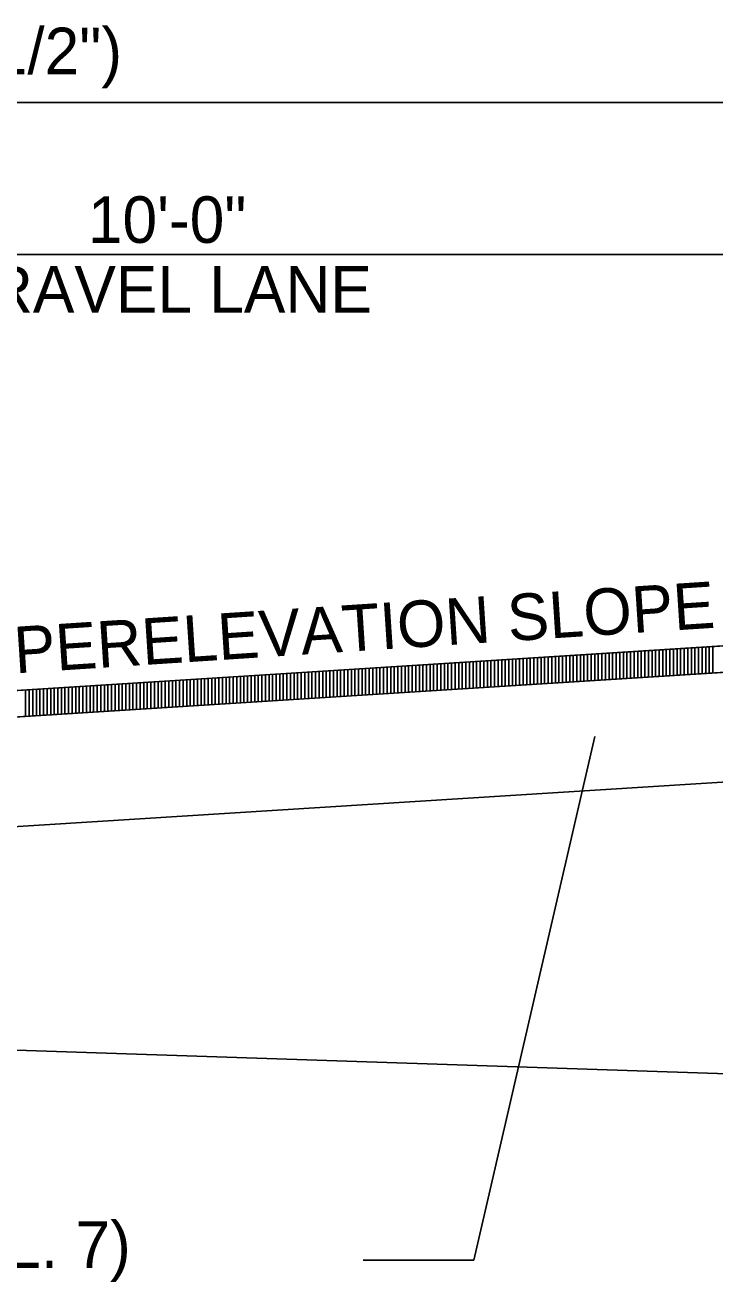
# Model space of a CAD drawing. Extents: x 1373719 to 1374161, y 379835 to 380167.
# Drawn here: x 1373967.18 to 1373976.82, y 379916.4 to 379933.96 of the extents above; entities that cross this region are included whole.
import ezdxf

# ---------------------------------------------------------------- set-up
doc = ezdxf.new("R2010")
doc.units = 0
for name, color, linetype in [('ACHM Surface', 7, 'Continuous'), ('Agg Base Course Text', 7, 'Continuous'), ('GREEN_TXT', 7, 'Continuous'), ('Pavement Layers', 7, 'Continuous'), ('SIGNATURE', 7, 'Continuous'), ('T_Drafting', 7, 'Continuous')]:
    doc.layers.add(name, color=color, linetype=linetype)

msp = doc.modelspace()

# ---------------------------------------------------------------- linework, layer by layer
for p, q in [((1373962.025, 379924.35), (1373981.525, 379925.58)), ((1373962.025, 379922.447), (1373986.325, 379923.98))]:
    msp.add_line(p, q)
at = {"layer": 'ACHM Surface'}
for p, q in [((1373975.388, 379924.823), (1373975.388, 379925.193)), ((1373975.438, 379924.826), (1373975.438, 379925.196)), ((1373975.488, 379924.829), (1373975.488, 379925.199)), ((1373975.538, 379924.832), (1373975.538, 379925.202)), ((1373975.588, 379924.835), (1373975.588, 379925.205)), ((1373975.638, 379924.838), (1373975.638, 379925.209)), ((1373975.688, 379924.842), (1373975.688, 379925.212)), ((1373975.738, 379924.845), (1373975.738, 379925.215)), ((1373975.788, 379924.848), (1373975.788, 379925.218)), ((1373975.838, 379924.851), (1373975.838, 379925.221)), ((1373975.888, 379924.854), (1373975.888, 379925.224)), ((1373975.938, 379924.857), (1373975.938, 379925.228)), ((1373975.988, 379924.86), (1373975.988, 379925.231)), ((1373976.038, 379924.864), (1373976.038, 379925.234)), ((1373976.088, 379924.867), (1373976.088, 379925.237)), ((1373976.138, 379924.87), (1373976.138, 379925.24)), ((1373976.188, 379924.873), (1373976.188, 379925.243)), ((1373976.238, 379924.876), (1373976.238, 379925.247)), ((1373976.288, 379924.879), (1373976.288, 379925.25)), ((1373976.338, 379924.883), (1373976.338, 379925.253)), ((1373976.388, 379924.886), (1373976.388, 379925.256)), ((1373976.438, 379924.889), (1373976.438, 379925.259)), ((1373976.488, 379924.892), (1373976.488, 379925.262)), ((1373976.538, 379924.895), (1373976.538, 379925.265)), ((1373976.588, 379924.898), (1373976.588, 379925.269)), ((1373976.638, 379924.902), (1373976.638, 379925.272)), ((1373976.688, 379924.905), (1373976.688, 379925.275)), ((1373976.738, 379924.908), (1373976.738, 379925.278)), ((1373976.788, 379924.911), (1373976.788, 379925.281)), ((1373972.638, 379924.649), (1373972.638, 379925.019)), ((1373972.688, 379924.652), (1373972.688, 379925.022)), ((1373972.738, 379924.655), (1373972.738, 379925.026)), ((1373972.788, 379924.659), (1373972.788, 379925.029)), ((1373972.838, 379924.662), (1373972.838, 379925.032)), ((1373972.888, 379924.665), (1373972.888, 379925.035)), ((1373972.938, 379924.668), (1373972.938, 379925.038)), ((1373972.988, 379924.671), (1373972.988, 379925.041)), ((1373973.038, 379924.674), (1373973.038, 379925.045)), ((1373973.088, 379924.677), (1373973.088, 379925.048)), ((1373973.138, 379924.681), (1373973.138, 379925.051)), ((1373973.188, 379924.684), (1373973.188, 379925.054)), ((1373973.238, 379924.687), (1373973.238, 379925.057)), ((1373973.288, 379924.69), (1373973.288, 379925.06)), ((1373973.338, 379924.693), (1373973.338, 379925.064)), ((1373973.388, 379924.696), (1373973.388, 379925.067)), ((1373973.438, 379924.7), (1373973.438, 379925.07)), ((1373973.488, 379924.703), (1373973.488, 379925.073)), ((1373973.538, 379924.706), (1373973.538, 379925.076)), ((1373973.588, 379924.709), (1373973.588, 379925.079)), ((1373973.638, 379924.712), (1373973.638, 379925.082)), ((1373973.688, 379924.715), (1373973.688, 379925.086)), ((1373973.738, 379924.719), (1373973.738, 379925.089)), ((1373973.788, 379924.722), (1373973.788, 379925.092)), ((1373973.838, 379924.725), (1373973.838, 379925.095)), ((1373973.888, 379924.728), (1373973.888, 379925.098)), ((1373973.938, 379924.731), (1373973.938, 379925.101)), ((1373973.988, 379924.734), (1373973.988, 379925.105)), ((1373974.038, 379924.737), (1373974.038, 379925.108)), ((1373974.088, 379924.741), (1373974.088, 379925.111)), ((1373974.138, 379924.744), (1373974.138, 379925.114)), ((1373974.188, 379924.747), (1373974.188, 379925.117)), ((1373974.238, 379924.75), (1373974.238, 379925.12)), ((1373974.288, 379924.753), (1373974.288, 379925.123)), ((1373974.338, 379924.756), (1373974.338, 379925.127)), ((1373974.388, 379924.76), (1373974.388, 379925.13)), ((1373974.438, 379924.763), (1373974.438, 379925.133)), ((1373974.488, 379924.766), (1373974.488, 379925.136)), ((1373974.538, 379924.769), (1373974.538, 379925.139)), ((1373974.588, 379924.772), (1373974.588, 379925.142)), ((1373974.638, 379924.775), (1373974.638, 379925.146)), ((1373974.688, 379924.778), (1373974.688, 379925.149)), ((1373974.738, 379924.782), (1373974.738, 379925.152)), ((1373974.788, 379924.785), (1373974.788, 379925.155)), ((1373974.838, 379924.788), (1373974.838, 379925.158)), ((1373974.888, 379924.791), (1373974.888, 379925.161)), ((1373974.938, 379924.794), (1373974.938, 379925.164)), ((1373974.988, 379924.797), (1373974.988, 379925.168)), ((1373975.038, 379924.801), (1373975.038, 379925.171)), ((1373975.088, 379924.804), (1373975.088, 379925.174)), ((1373975.138, 379924.807), (1373975.138, 379925.177)), ((1373975.188, 379924.81), (1373975.188, 379925.18)), ((1373975.238, 379924.813), (1373975.238, 379925.183)), ((1373975.288, 379924.816), (1373975.288, 379925.187)), ((1373975.338, 379924.819), (1373975.338, 379925.19)), ((1373969.838, 379924.472), (1373969.838, 379924.843)), ((1373969.888, 379924.476), (1373969.888, 379924.846)), ((1373969.938, 379924.479), (1373969.938, 379924.849)), ((1373969.988, 379924.482), (1373969.988, 379924.852)), ((1373970.038, 379924.485), (1373970.038, 379924.855)), ((1373970.088, 379924.488), (1373970.088, 379924.858)), ((1373970.138, 379924.491), (1373970.138, 379924.862)), ((1373970.188, 379924.494), (1373970.188, 379924.865)), ((1373970.238, 379924.498), (1373970.238, 379924.868)), ((1373970.288, 379924.501), (1373970.288, 379924.871)), ((1373970.338, 379924.504), (1373970.338, 379924.874)), ((1373970.388, 379924.507), (1373970.388, 379924.877)), ((1373970.438, 379924.51), (1373970.438, 379924.88)), ((1373970.488, 379924.513), (1373970.488, 379924.884)), ((1373970.538, 379924.517), (1373970.538, 379924.887)), ((1373970.588, 379924.52), (1373970.588, 379924.89)), ((1373970.638, 379924.523), (1373970.638, 379924.893)), ((1373970.688, 379924.526), (1373970.688, 379924.896)), ((1373970.738, 379924.529), (1373970.738, 379924.899)), ((1373970.788, 379924.532), (1373970.788, 379924.903)), ((1373970.838, 379924.535), (1373970.838, 379924.906)), ((1373970.888, 379924.539), (1373970.888, 379924.909)), ((1373970.938, 379924.542), (1373970.938, 379924.912)), ((1373970.988, 379924.545), (1373970.988, 379924.915)), ((1373971.038, 379924.548), (1373971.038, 379924.918)), ((1373971.088, 379924.551), (1373971.088, 379924.922)), ((1373971.138, 379924.554), (1373971.138, 379924.925)), ((1373971.188, 379924.558), (1373971.188, 379924.928)), ((1373971.238, 379924.561), (1373971.238, 379924.931)), ((1373971.288, 379924.564), (1373971.288, 379924.934)), ((1373971.338, 379924.567), (1373971.338, 379924.937)), ((1373971.388, 379924.57), (1373971.388, 379924.94)), ((1373971.438, 379924.573), (1373971.438, 379924.944)), ((1373971.488, 379924.577), (1373971.488, 379924.947)), ((1373971.538, 379924.58), (1373971.538, 379924.95)), ((1373971.588, 379924.583), (1373971.588, 379924.953)), ((1373971.638, 379924.586), (1373971.638, 379924.956)), ((1373971.688, 379924.589), (1373971.688, 379924.959)), ((1373971.738, 379924.592), (1373971.738, 379924.963)), ((1373971.788, 379924.595), (1373971.788, 379924.966)), ((1373971.838, 379924.599), (1373971.838, 379924.969)), ((1373971.888, 379924.602), (1373971.888, 379924.972)), ((1373971.938, 379924.605), (1373971.938, 379924.975)), ((1373971.988, 379924.608), (1373971.988, 379924.978)), ((1373972.038, 379924.611), (1373972.038, 379924.981)), ((1373972.088, 379924.614), (1373972.088, 379924.985)), ((1373972.138, 379924.618), (1373972.138, 379924.988)), ((1373972.188, 379924.621), (1373972.188, 379924.991)), ((1373972.238, 379924.624), (1373972.238, 379924.994)), ((1373972.288, 379924.627), (1373972.288, 379924.997)), ((1373972.338, 379924.63), (1373972.338, 379925)), ((1373972.388, 379924.633), (1373972.388, 379925.004)), ((1373972.438, 379924.636), (1373972.438, 379925.007)), ((1373972.488, 379924.64), (1373972.488, 379925.01)), ((1373972.538, 379924.643), (1373972.538, 379925.013)), ((1373972.588, 379924.646), (1373972.588, 379925.016)), ((1373967.188, 379924.305), (1373967.188, 379924.675)), ((1373967.238, 379924.308), (1373967.238, 379924.679)), ((1373967.288, 379924.311), (1373967.288, 379924.682)), ((1373967.338, 379924.315), (1373967.338, 379924.685)), ((1373967.388, 379924.318), (1373967.388, 379924.688)), ((1373967.438, 379924.321), (1373967.438, 379924.691)), ((1373967.488, 379924.324), (1373967.488, 379924.694)), ((1373967.538, 379924.327), (1373967.538, 379924.697)), ((1373967.588, 379924.33), (1373967.588, 379924.701)), ((1373967.638, 379924.334), (1373967.638, 379924.704)), ((1373967.688, 379924.337), (1373967.688, 379924.707)), ((1373967.738, 379924.34), (1373967.738, 379924.71)), ((1373967.788, 379924.343), (1373967.788, 379924.713)), ((1373967.838, 379924.346), (1373967.838, 379924.716)), ((1373967.888, 379924.349), (1373967.888, 379924.72)), ((1373967.938, 379924.352), (1373967.938, 379924.723)), ((1373967.988, 379924.356), (1373967.988, 379924.726)), ((1373968.038, 379924.359), (1373968.038, 379924.729)), ((1373968.088, 379924.362), (1373968.088, 379924.732)), ((1373968.138, 379924.365), (1373968.138, 379924.735)), ((1373968.188, 379924.368), (1373968.188, 379924.739)), ((1373968.238, 379924.371), (1373968.238, 379924.742)), ((1373968.288, 379924.375), (1373968.288, 379924.745)), ((1373968.338, 379924.378), (1373968.338, 379924.748)), ((1373968.388, 379924.381), (1373968.388, 379924.751)), ((1373968.438, 379924.384), (1373968.438, 379924.754)), ((1373968.488, 379924.387), (1373968.488, 379924.757)), ((1373968.538, 379924.39), (1373968.538, 379924.761)), ((1373968.588, 379924.394), (1373968.588, 379924.764)), ((1373968.638, 379924.397), (1373968.638, 379924.767)), ((1373968.688, 379924.4), (1373968.688, 379924.77)), ((1373968.738, 379924.403), (1373968.738, 379924.773)), ((1373968.788, 379924.406), (1373968.788, 379924.776)), ((1373968.838, 379924.409), (1373968.838, 379924.78)), ((1373968.888, 379924.412), (1373968.888, 379924.783)), ((1373968.938, 379924.416), (1373968.938, 379924.786)), ((1373968.988, 379924.419), (1373968.988, 379924.789)), ((1373969.038, 379924.422), (1373969.038, 379924.792)), ((1373969.088, 379924.425), (1373969.088, 379924.795)), ((1373969.138, 379924.428), (1373969.138, 379924.798)), ((1373969.188, 379924.431), (1373969.188, 379924.802)), ((1373969.238, 379924.435), (1373969.238, 379924.805)), ((1373969.288, 379924.438), (1373969.288, 379924.808)), ((1373969.338, 379924.441), (1373969.338, 379924.811)), ((1373969.388, 379924.444), (1373969.388, 379924.814)), ((1373969.438, 379924.447), (1373969.438, 379924.817)), ((1373969.488, 379924.45), (1373969.488, 379924.821)), ((1373969.538, 379924.453), (1373969.538, 379924.824)), ((1373969.588, 379924.457), (1373969.588, 379924.827)), ((1373969.638, 379924.46), (1373969.638, 379924.83)), ((1373969.688, 379924.463), (1373969.688, 379924.833)), ((1373969.738, 379924.466), (1373969.738, 379924.836)), ((1373969.788, 379924.469), (1373969.788, 379924.839))]:
    msp.add_line(p, q, dxfattribs=at)
at = {"layer": 'Agg Base Course Text'}
msp.add_lwpolyline([(1373971.904, 379916.71), (1373973.447, 379916.71), (1373975.139, 379924.026)], dxfattribs=at)
at = {"layer": 'GREEN_TXT'}
for p, q in [((1373981.525, 379932.884), (1373942.525, 379932.884)), ((1373978.525, 379930.758), (1373962.025, 379930.758))]:
    msp.add_line(p, q, dxfattribs=at)
at = {"layer": 'Pavement Layers'}
msp.add_line((1373962.025, 379923.979), (1373981.525, 379925.21), dxfattribs=at)
at = {"layer": 'SIGNATURE'}
msp.add_lwpolyline([(1373942.525, 379922.749), (1373942.92, 379923.144), (1373962.025, 379924.35), (1373981.176, 379925.558), (1373981.525, 379925.21), (1373962.025, 379923.979)], close=True, dxfattribs=at)
at = {"layer": 'T_Drafting'}
msp.add_lwpolyline([(1373909.628, 379921.87), (1373922.475, 379921.802), (1373942.6, 379919.022), (1373967.061, 379919.641), (1373996.432, 379918.665), (1374003.428, 379918.279), (1374018.955, 379918.279)], dxfattribs=at)

# ---------------------------------------------------------------- texts
at = {"layer": 'GREEN_TXT'}
for s, p in [('24\'-0" ACHM SURFACE COURSE (1/2") ', (1373952.828, 379933.278)), ('10\'-0"', (1373968.058, 379930.921)), ('TRAVEL LANE', (1373966.131, 379929.946)), ('20\'-0" AGGREGATE BASE CRSE. (CL. 7)', (1373952.339, 379916.6))]:
    msp.add_text(s, height=0.65, dxfattribs=at).set_placement(p)
msp.add_text('SUPERELEVATION SLOPE', height=0.65, rotation=3.7342, dxfattribs=at).set_placement((1373965.841, 379924.827))

doc.saveas('drawing.dxf')
